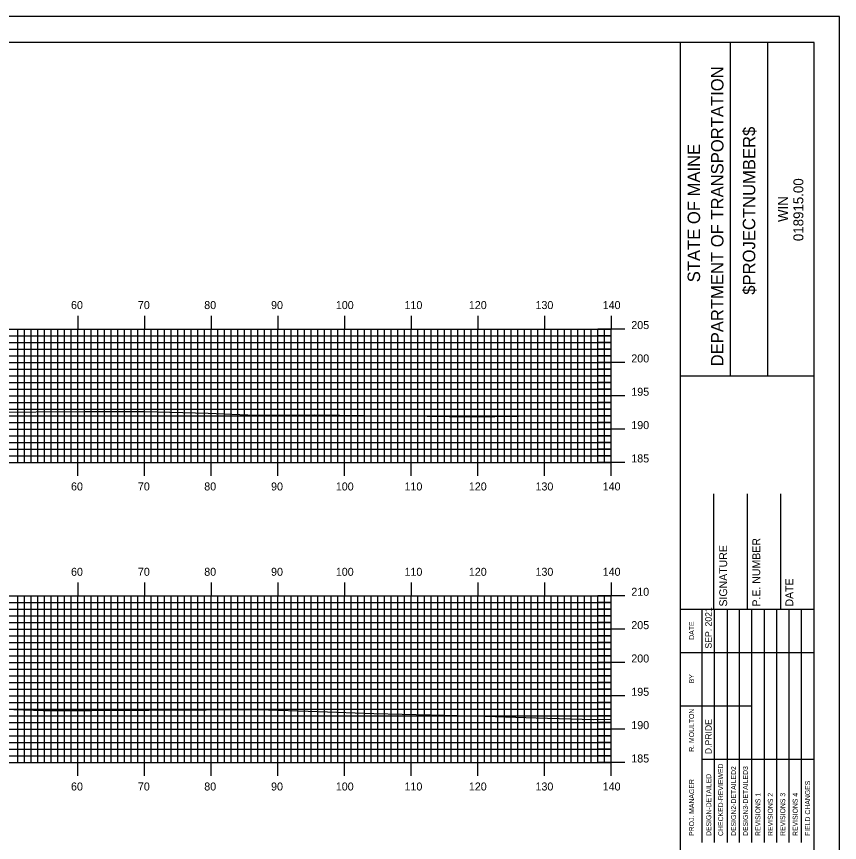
# Model space of a CAD drawing. Extents: x 1814128 to 1814471, y 442591 to 442811.
# Drawn here: x 1814344.8 to 1814468.2, y 442686.7 to 442810.5 of the extents above; entities that cross this region are included whole.
import ezdxf

# ---------------------------------------------------------------- set-up
doc = ezdxf.new("R2010")
doc.units = 0
for name, color, linetype in [('BORDER', 7, 'Continuous'), ('H_V ANNOTATION', 7, 'Continuous'), ('MAJOR', 7, 'Continuous'), ('MINOR', 7, 'Continuous'), ('PLOT BOUNDARY', 7, 'Continuous'), ('S_Roadway_Centerline', 7, 'Continuous')]:
    doc.layers.add(name, color=color, linetype=linetype)

msp = doc.modelspace()

# ---------------------------------------------------------------- linework, layer by layer
at = {"layer": 'BORDER'}
for p, q in [((1814444.39, 442596.67), (1814444.39, 442806.67)), ((1814451.85, 442756.66), (1814451.85, 442806.66)), ((1814457.44, 442756.66), (1814457.44, 442806.66)), ((1814444.4, 442756.65), (1814464.39, 442756.65)), ((1814449.39, 442721.67), (1814449.39, 442738.97)), ((1814454.39, 442721.67), (1814454.39, 442738.97)), ((1814459.39, 442721.67), (1814459.39, 442738.97)), ((1814444.39, 442721.67), (1814464.39, 442721.67))]:
    msp.add_line(p, q, dxfattribs=at)
msp.add_lwpolyline([(1814144.39, 442596.67), (1814464.39, 442596.67), (1814464.39, 442806.67), (1814144.39, 442806.67)], close=True, dxfattribs=at)
for points in [[(1814447.62, 442715.17), (1814447.62, 442721.67)], [(1814449.49, 442686.68), (1814449.49, 442721.67)], [(1814451.35, 442721.67), (1814451.35, 442686.68)], [(1814453.22, 442686.68), (1814453.22, 442721.67)], [(1814455.08, 442686.68), (1814455.08, 442721.67)], [(1814456.94, 442686.68), (1814456.94, 442721.67)], [(1814458.81, 442686.68), (1814458.81, 442721.67)], [(1814460.67, 442686.68), (1814460.67, 442721.67)], [(1814462.53, 442686.68), (1814462.53, 442721.67)], [(1814447.63, 442686.68), (1814447.63, 442720.26)], [(1814444.39, 442715.17), (1814464.39, 442715.17)], [(1814444.39, 442707.17), (1814447.63, 442707.17)], [(1814447.62, 442707.17), (1814455.08, 442707.17)], [(1814447.62, 442699.17), (1814464.39, 442699.17)]]:
    msp.add_lwpolyline(points, dxfattribs=at)
at = {"layer": 'MAJOR'}
for p, q in [((1814353.99, 442765.67), (1814353.99, 442763.67)), ((1814363.99, 442765.67), (1814363.99, 442763.67)), ((1814373.99, 442765.67), (1814373.99, 442763.67)), ((1814383.99, 442765.67), (1814383.99, 442763.67)), ((1814393.99, 442765.67), (1814393.99, 442763.67)), ((1814403.99, 442765.67), (1814403.99, 442763.67)), ((1814413.99, 442765.67), (1814413.99, 442763.67)), ((1814423.99, 442765.67), (1814423.99, 442763.67)), ((1814433.99, 442765.67), (1814433.99, 442763.67)), ((1814153.99, 442763.67), (1814433.99, 442763.67)), ((1814153.99, 442763.67), (1814433.99, 442763.67)), ((1814353.99, 442743.67), (1814353.99, 442763.67)), ((1814363.99, 442743.67), (1814363.99, 442763.67)), ((1814373.99, 442743.67), (1814373.99, 442763.67)), ((1814383.99, 442743.67), (1814383.99, 442763.67)), ((1814393.99, 442743.67), (1814393.99, 442763.67)), ((1814403.99, 442743.67), (1814403.99, 442763.67)), ((1814413.99, 442743.67), (1814413.99, 442763.67)), ((1814423.99, 442743.67), (1814423.99, 442763.67)), ((1814436, 442763.67), (1814431.99, 442763.67)), ((1814433.99, 442743.67), (1814433.99, 442763.67)), ((1814433.99, 442743.67), (1814433.99, 442763.67)), ((1814153.99, 442758.67), (1814433.99, 442758.67)), ((1814436, 442758.67), (1814431.99, 442758.67)), ((1814153.99, 442753.67), (1814433.99, 442753.67)), ((1814436, 442753.67), (1814431.99, 442753.67)), ((1814153.99, 442748.67), (1814433.99, 442748.67)), ((1814436, 442748.67), (1814431.99, 442748.67)), ((1814153.99, 442743.67), (1814433.99, 442743.67)), ((1814153.99, 442743.67), (1814433.99, 442743.67)), ((1814353.99, 442741.66), (1814353.99, 442743.67)), ((1814363.99, 442741.66), (1814363.99, 442743.67)), ((1814373.99, 442741.66), (1814373.99, 442743.67)), ((1814383.99, 442741.66), (1814383.99, 442743.67)), ((1814393.99, 442741.66), (1814393.99, 442743.67)), ((1814403.99, 442741.66), (1814403.99, 442743.67)), ((1814413.99, 442741.66), (1814413.99, 442743.67)), ((1814423.99, 442741.66), (1814423.99, 442743.67)), ((1814436, 442743.67), (1814431.99, 442743.67)), ((1814433.99, 442741.66), (1814433.99, 442743.67)), ((1814353.99, 442725.67), (1814353.99, 442723.67)), ((1814363.99, 442725.67), (1814363.99, 442723.67)), ((1814373.99, 442725.67), (1814373.99, 442723.67)), ((1814383.99, 442725.67), (1814383.99, 442723.67)), ((1814393.99, 442725.67), (1814393.99, 442723.67)), ((1814403.99, 442725.67), (1814403.99, 442723.67)), ((1814413.99, 442725.67), (1814413.99, 442723.67)), ((1814423.99, 442725.67), (1814423.99, 442723.67)), ((1814433.99, 442725.67), (1814433.99, 442723.67)), ((1814153.99, 442723.67), (1814433.99, 442723.67)), ((1814153.99, 442723.67), (1814433.99, 442723.67)), ((1814353.99, 442698.67), (1814353.99, 442723.67)), ((1814363.99, 442698.67), (1814363.99, 442723.67)), ((1814373.99, 442698.67), (1814373.99, 442723.67)), ((1814383.99, 442698.67), (1814383.99, 442723.67)), ((1814393.99, 442698.67), (1814393.99, 442723.67)), ((1814403.99, 442698.67), (1814403.99, 442723.67)), ((1814413.99, 442698.67), (1814413.99, 442723.67)), ((1814423.99, 442698.67), (1814423.99, 442723.67)), ((1814436, 442723.67), (1814431.99, 442723.67)), ((1814433.99, 442698.67), (1814433.99, 442723.67)), ((1814433.99, 442698.67), (1814433.99, 442723.67)), ((1814153.99, 442718.67), (1814433.99, 442718.67)), ((1814436, 442718.67), (1814431.99, 442718.67)), ((1814153.99, 442713.67), (1814433.99, 442713.67)), ((1814436, 442713.67), (1814431.99, 442713.67)), ((1814153.99, 442708.67), (1814433.99, 442708.67)), ((1814436, 442708.67), (1814431.99, 442708.67)), ((1814153.99, 442703.67), (1814433.99, 442703.67)), ((1814436, 442703.67), (1814431.99, 442703.67)), ((1814153.99, 442698.67), (1814433.99, 442698.67)), ((1814153.99, 442698.67), (1814433.99, 442698.67)), ((1814353.99, 442696.66), (1814353.99, 442698.67)), ((1814363.99, 442696.66), (1814363.99, 442698.67)), ((1814373.99, 442696.66), (1814373.99, 442698.67)), ((1814383.99, 442696.66), (1814383.99, 442698.67)), ((1814393.99, 442696.66), (1814393.99, 442698.67)), ((1814403.99, 442696.66), (1814403.99, 442698.67)), ((1814413.99, 442696.66), (1814413.99, 442698.67)), ((1814423.99, 442696.66), (1814423.99, 442698.67)), ((1814436, 442698.67), (1814431.99, 442698.67)), ((1814433.99, 442696.66), (1814433.99, 442698.67))]:
    msp.add_line(p, q, dxfattribs=at)
at = {"layer": 'MINOR'}
for p, q in [((1814344.99, 442743.67), (1814344.99, 442763.67)), ((1814345.99, 442743.67), (1814345.99, 442763.67)), ((1814346.99, 442743.67), (1814346.99, 442763.67)), ((1814347.99, 442743.67), (1814347.99, 442763.67)), ((1814348.99, 442743.67), (1814348.99, 442763.67)), ((1814349.99, 442743.67), (1814349.99, 442763.67)), ((1814350.99, 442743.67), (1814350.99, 442763.67)), ((1814351.99, 442743.67), (1814351.99, 442763.67)), ((1814352.99, 442743.67), (1814352.99, 442763.67)), ((1814354.99, 442743.67), (1814354.99, 442763.67)), ((1814355.99, 442743.67), (1814355.99, 442763.67)), ((1814356.99, 442743.67), (1814356.99, 442763.67)), ((1814357.99, 442743.67), (1814357.99, 442763.67)), ((1814358.99, 442743.67), (1814358.99, 442763.67)), ((1814359.99, 442743.67), (1814359.99, 442763.67)), ((1814360.99, 442743.67), (1814360.99, 442763.67)), ((1814361.99, 442743.67), (1814361.99, 442763.67)), ((1814362.99, 442743.67), (1814362.99, 442763.67)), ((1814364.99, 442743.67), (1814364.99, 442763.67)), ((1814365.99, 442743.67), (1814365.99, 442763.67)), ((1814366.99, 442743.67), (1814366.99, 442763.67)), ((1814367.99, 442743.67), (1814367.99, 442763.67)), ((1814368.99, 442743.67), (1814368.99, 442763.67)), ((1814369.99, 442743.67), (1814369.99, 442763.67)), ((1814370.99, 442743.67), (1814370.99, 442763.67)), ((1814371.99, 442743.67), (1814371.99, 442763.67)), ((1814372.99, 442743.67), (1814372.99, 442763.67)), ((1814374.99, 442743.67), (1814374.99, 442763.67)), ((1814375.99, 442743.67), (1814375.99, 442763.67)), ((1814376.99, 442743.67), (1814376.99, 442763.67)), ((1814377.99, 442743.67), (1814377.99, 442763.67)), ((1814378.99, 442743.67), (1814378.99, 442763.67)), ((1814379.99, 442743.67), (1814379.99, 442763.67)), ((1814380.99, 442743.67), (1814380.99, 442763.67)), ((1814381.99, 442743.67), (1814381.99, 442763.67)), ((1814382.99, 442743.67), (1814382.99, 442763.67)), ((1814384.99, 442743.67), (1814384.99, 442763.67)), ((1814385.99, 442743.67), (1814385.99, 442763.67)), ((1814386.99, 442743.67), (1814386.99, 442763.67)), ((1814387.99, 442743.67), (1814387.99, 442763.67)), ((1814388.99, 442743.67), (1814388.99, 442763.67)), ((1814389.99, 442743.67), (1814389.99, 442763.67)), ((1814390.99, 442743.67), (1814390.99, 442763.67)), ((1814391.99, 442743.67), (1814391.99, 442763.67)), ((1814392.99, 442743.67), (1814392.99, 442763.67)), ((1814394.99, 442743.67), (1814394.99, 442763.67)), ((1814395.99, 442743.67), (1814395.99, 442763.67)), ((1814396.99, 442743.67), (1814396.99, 442763.67)), ((1814397.99, 442743.67), (1814397.99, 442763.67)), ((1814398.99, 442743.67), (1814398.99, 442763.67)), ((1814399.99, 442743.67), (1814399.99, 442763.67)), ((1814400.99, 442743.67), (1814400.99, 442763.67)), ((1814401.99, 442743.67), (1814401.99, 442763.67)), ((1814402.99, 442743.67), (1814402.99, 442763.67)), ((1814404.99, 442743.67), (1814404.99, 442763.67)), ((1814405.99, 442743.67), (1814405.99, 442763.67)), ((1814406.99, 442743.67), (1814406.99, 442763.67)), ((1814407.99, 442743.67), (1814407.99, 442763.67)), ((1814408.99, 442743.67), (1814408.99, 442763.67)), ((1814409.99, 442743.67), (1814409.99, 442763.67)), ((1814410.99, 442743.67), (1814410.99, 442763.67)), ((1814411.99, 442743.67), (1814411.99, 442763.67)), ((1814412.99, 442743.67), (1814412.99, 442763.67)), ((1814414.99, 442743.67), (1814414.99, 442763.67)), ((1814415.99, 442743.67), (1814415.99, 442763.67)), ((1814416.99, 442743.67), (1814416.99, 442763.67)), ((1814417.99, 442743.67), (1814417.99, 442763.67)), ((1814418.99, 442743.67), (1814418.99, 442763.67)), ((1814419.99, 442743.67), (1814419.99, 442763.67)), ((1814420.99, 442743.67), (1814420.99, 442763.67)), ((1814421.99, 442743.67), (1814421.99, 442763.67)), ((1814422.99, 442743.67), (1814422.99, 442763.67)), ((1814424.99, 442743.67), (1814424.99, 442763.67)), ((1814425.99, 442743.67), (1814425.99, 442763.67)), ((1814426.99, 442743.67), (1814426.99, 442763.67)), ((1814427.99, 442743.67), (1814427.99, 442763.67)), ((1814428.99, 442743.67), (1814428.99, 442763.67)), ((1814429.99, 442743.67), (1814429.99, 442763.67)), ((1814430.99, 442743.67), (1814430.99, 442763.67)), ((1814431.99, 442743.67), (1814431.99, 442763.67)), ((1814432.99, 442743.67), (1814432.99, 442763.67)), ((1814153.99, 442762.67), (1814433.99, 442762.67)), ((1814433.99, 442762.67), (1814431.99, 442762.67)), ((1814153.99, 442761.67), (1814433.99, 442761.67)), ((1814433.99, 442761.67), (1814431.99, 442761.67)), ((1814153.99, 442760.67), (1814433.99, 442760.67)), ((1814433.99, 442760.67), (1814431.99, 442760.67)), ((1814153.99, 442759.67), (1814433.99, 442759.67)), ((1814433.99, 442759.67), (1814431.99, 442759.67)), ((1814153.99, 442757.67), (1814433.99, 442757.67)), ((1814433.99, 442757.67), (1814431.99, 442757.67)), ((1814153.99, 442756.67), (1814433.99, 442756.67)), ((1814433.99, 442756.67), (1814431.99, 442756.67)), ((1814153.99, 442755.67), (1814433.99, 442755.67)), ((1814433.99, 442755.67), (1814431.99, 442755.67)), ((1814153.99, 442754.67), (1814433.99, 442754.67)), ((1814433.99, 442754.67), (1814431.99, 442754.67)), ((1814153.99, 442752.67), (1814433.99, 442752.67)), ((1814433.99, 442752.67), (1814431.99, 442752.67)), ((1814153.99, 442751.67), (1814433.99, 442751.67)), ((1814433.99, 442751.67), (1814431.99, 442751.67)), ((1814153.99, 442750.67), (1814433.99, 442750.67)), ((1814433.99, 442750.67), (1814431.99, 442750.67)), ((1814153.99, 442749.67), (1814433.99, 442749.67)), ((1814433.99, 442749.67), (1814431.99, 442749.67)), ((1814153.99, 442747.67), (1814433.99, 442747.67)), ((1814433.99, 442747.67), (1814431.99, 442747.67)), ((1814153.99, 442746.67), (1814433.99, 442746.67)), ((1814433.99, 442746.67), (1814431.99, 442746.67)), ((1814153.99, 442745.67), (1814433.99, 442745.67)), ((1814433.99, 442745.67), (1814431.99, 442745.67)), ((1814153.99, 442744.67), (1814433.99, 442744.67)), ((1814433.99, 442744.67), (1814431.99, 442744.67)), ((1814344.99, 442698.67), (1814344.99, 442723.67)), ((1814345.99, 442698.67), (1814345.99, 442723.67)), ((1814346.99, 442698.67), (1814346.99, 442723.67)), ((1814347.99, 442698.67), (1814347.99, 442723.67)), ((1814348.99, 442698.67), (1814348.99, 442723.67)), ((1814349.99, 442698.67), (1814349.99, 442723.67)), ((1814350.99, 442698.67), (1814350.99, 442723.67)), ((1814351.99, 442698.67), (1814351.99, 442723.67)), ((1814352.99, 442698.67), (1814352.99, 442723.67)), ((1814354.99, 442698.67), (1814354.99, 442723.67)), ((1814355.99, 442698.67), (1814355.99, 442723.67)), ((1814356.99, 442698.67), (1814356.99, 442723.67)), ((1814357.99, 442698.67), (1814357.99, 442723.67)), ((1814358.99, 442698.67), (1814358.99, 442723.67)), ((1814359.99, 442698.67), (1814359.99, 442723.67)), ((1814360.99, 442698.67), (1814360.99, 442723.67)), ((1814361.99, 442698.67), (1814361.99, 442723.67)), ((1814362.99, 442698.67), (1814362.99, 442723.67)), ((1814364.99, 442698.67), (1814364.99, 442723.67)), ((1814365.99, 442698.67), (1814365.99, 442723.67)), ((1814366.99, 442698.67), (1814366.99, 442723.67)), ((1814367.99, 442698.67), (1814367.99, 442723.67)), ((1814368.99, 442698.67), (1814368.99, 442723.67)), ((1814369.99, 442698.67), (1814369.99, 442723.67)), ((1814370.99, 442698.67), (1814370.99, 442723.67)), ((1814371.99, 442698.67), (1814371.99, 442723.67)), ((1814372.99, 442698.67), (1814372.99, 442723.67)), ((1814374.99, 442698.67), (1814374.99, 442723.67)), ((1814375.99, 442698.67), (1814375.99, 442723.67)), ((1814376.99, 442698.67), (1814376.99, 442723.67)), ((1814377.99, 442698.67), (1814377.99, 442723.67)), ((1814378.99, 442698.67), (1814378.99, 442723.67)), ((1814379.99, 442698.67), (1814379.99, 442723.67)), ((1814380.99, 442698.67), (1814380.99, 442723.67)), ((1814381.99, 442698.67), (1814381.99, 442723.67)), ((1814382.99, 442698.67), (1814382.99, 442723.67)), ((1814384.99, 442698.67), (1814384.99, 442723.67)), ((1814385.99, 442698.67), (1814385.99, 442723.67)), ((1814386.99, 442698.67), (1814386.99, 442723.67)), ((1814387.99, 442698.67), (1814387.99, 442723.67)), ((1814388.99, 442698.67), (1814388.99, 442723.67)), ((1814389.99, 442698.67), (1814389.99, 442723.67)), ((1814390.99, 442698.67), (1814390.99, 442723.67)), ((1814391.99, 442698.67), (1814391.99, 442723.67)), ((1814392.99, 442698.67), (1814392.99, 442723.67)), ((1814394.99, 442698.67), (1814394.99, 442723.67)), ((1814395.99, 442698.67), (1814395.99, 442723.67)), ((1814396.99, 442698.67), (1814396.99, 442723.67)), ((1814397.99, 442698.67), (1814397.99, 442723.67)), ((1814398.99, 442698.67), (1814398.99, 442723.67)), ((1814399.99, 442698.67), (1814399.99, 442723.67)), ((1814400.99, 442698.67), (1814400.99, 442723.67)), ((1814401.99, 442698.67), (1814401.99, 442723.67)), ((1814402.99, 442698.67), (1814402.99, 442723.67)), ((1814404.99, 442698.67), (1814404.99, 442723.67)), ((1814405.99, 442698.67), (1814405.99, 442723.67)), ((1814406.99, 442698.67), (1814406.99, 442723.67)), ((1814407.99, 442698.67), (1814407.99, 442723.67)), ((1814408.99, 442698.67), (1814408.99, 442723.67)), ((1814409.99, 442698.67), (1814409.99, 442723.67)), ((1814410.99, 442698.67), (1814410.99, 442723.67)), ((1814411.99, 442698.67), (1814411.99, 442723.67)), ((1814412.99, 442698.67), (1814412.99, 442723.67)), ((1814414.99, 442698.67), (1814414.99, 442723.67)), ((1814415.99, 442698.67), (1814415.99, 442723.67)), ((1814416.99, 442698.67), (1814416.99, 442723.67)), ((1814417.99, 442698.67), (1814417.99, 442723.67)), ((1814418.99, 442698.67), (1814418.99, 442723.67)), ((1814419.99, 442698.67), (1814419.99, 442723.67)), ((1814420.99, 442698.67), (1814420.99, 442723.67)), ((1814421.99, 442698.67), (1814421.99, 442723.67)), ((1814422.99, 442698.67), (1814422.99, 442723.67)), ((1814424.99, 442698.67), (1814424.99, 442723.67)), ((1814425.99, 442698.67), (1814425.99, 442723.67)), ((1814426.99, 442698.67), (1814426.99, 442723.67)), ((1814427.99, 442698.67), (1814427.99, 442723.67)), ((1814428.99, 442698.67), (1814428.99, 442723.67)), ((1814429.99, 442698.67), (1814429.99, 442723.67)), ((1814430.99, 442698.67), (1814430.99, 442723.67)), ((1814431.99, 442698.67), (1814431.99, 442723.67)), ((1814432.99, 442698.67), (1814432.99, 442723.67)), ((1814153.99, 442722.67), (1814433.99, 442722.67)), ((1814153.99, 442721.67), (1814433.99, 442721.67)), ((1814433.99, 442722.67), (1814431.99, 442722.67)), ((1814433.99, 442721.67), (1814431.99, 442721.67)), ((1814153.99, 442720.67), (1814433.99, 442720.67)), ((1814433.99, 442720.67), (1814431.99, 442720.67)), ((1814153.99, 442719.67), (1814433.99, 442719.67)), ((1814433.99, 442719.67), (1814431.99, 442719.67)), ((1814153.99, 442717.67), (1814433.99, 442717.67)), ((1814153.99, 442716.67), (1814433.99, 442716.67)), ((1814433.99, 442717.67), (1814431.99, 442717.67)), ((1814433.99, 442716.67), (1814431.99, 442716.67)), ((1814153.99, 442715.67), (1814433.99, 442715.67)), ((1814433.99, 442715.67), (1814431.99, 442715.67)), ((1814153.99, 442714.67), (1814433.99, 442714.67)), ((1814433.99, 442714.67), (1814431.99, 442714.67)), ((1814153.99, 442712.67), (1814433.99, 442712.67)), ((1814153.99, 442711.67), (1814433.99, 442711.67)), ((1814433.99, 442712.67), (1814431.99, 442712.67)), ((1814433.99, 442711.67), (1814431.99, 442711.67)), ((1814153.99, 442710.67), (1814433.99, 442710.67)), ((1814433.99, 442710.67), (1814431.99, 442710.67)), ((1814153.99, 442709.67), (1814433.99, 442709.67)), ((1814433.99, 442709.67), (1814431.99, 442709.67)), ((1814153.99, 442707.67), (1814433.99, 442707.67)), ((1814153.99, 442706.67), (1814433.99, 442706.67)), ((1814433.99, 442707.67), (1814431.99, 442707.67)), ((1814433.99, 442706.67), (1814431.99, 442706.67)), ((1814153.99, 442705.67), (1814433.99, 442705.67)), ((1814433.99, 442705.67), (1814431.99, 442705.67)), ((1814153.99, 442704.67), (1814433.99, 442704.67)), ((1814433.99, 442704.67), (1814431.99, 442704.67)), ((1814153.99, 442702.67), (1814433.99, 442702.67)), ((1814153.99, 442701.67), (1814433.99, 442701.67)), ((1814433.99, 442702.67), (1814431.99, 442702.67)), ((1814433.99, 442701.67), (1814431.99, 442701.67)), ((1814153.99, 442700.67), (1814433.99, 442700.67)), ((1814433.99, 442700.67), (1814431.99, 442700.67)), ((1814153.99, 442699.67), (1814433.99, 442699.67)), ((1814433.99, 442699.67), (1814431.99, 442699.67))]:
    msp.add_line(p, q, dxfattribs=at)
at = {"layer": 'PLOT BOUNDARY'}
msp.add_lwpolyline([(1814128.21, 442590.55), (1814468.21, 442590.55), (1814468.21, 442810.55), (1814128.21, 442810.55)], close=True, dxfattribs=at)
at = {"layer": 'S_Roadway_Centerline'}
for points in [[(1814340.44, 442751.22), (1814354.92, 442751.33), (1814364, 442751.32), (1814373.52, 442751.07), (1814380.7, 442750.78), (1814389.52, 442750.79), (1814396.94, 442750.73), (1814403.1, 442750.68), (1814413.04, 442750.53), (1814420.07, 442750.62), (1814430.03, 442750.71), (1814433.99, 442750.67)], [(1814341.4, 442706.74), (1814348.79, 442706.48), (1814356.11, 442706.45), (1814373.25, 442706.57), (1814381.06, 442706.62), (1814390.02, 442706.34), (1814398.38, 442706.03), (1814406.87, 442705.82), (1814415.07, 442705.63), (1814422.72, 442705.35), (1814431.34, 442705.13), (1814433.99, 442705.19)]]:
    msp.add_lwpolyline(points, dxfattribs=at)

# ---------------------------------------------------------------- texts
at = {"layer": 'BORDER'}
for s, height, p in [('DEPARTMENT OF TRANSPORTATION', 1.8635, (1814450.81, 442758.08)), ('$PROJECTNUMBER$', 1.8635, (1814455.58, 442768.82)), ('STATE OF MAINE', 1.8635, (1814447.3, 442770.69)), ('018915.00', 1.491, (1814462.79, 442776.86)), ('WIN', 1.491, (1814460.47, 442779.73)), ('P.E. NUMBER', 1.1811, (1814456.32, 442722.06)), ('SIGNATURE', 1.181, (1814451.36, 442722.06)), ('DATE', 1.181, (1814461.28, 442722.06)), ('SEP. 2021', 0.969, (1814449.04, 442715.76)), ('DATE', 0.743, (1814446.4, 442717.08)), ('BY', 0.743, (1814446.4, 442710.54)), ('R. MOULTON', 0.745, (1814446.4, 442700.28)), ('D.PRIDE', 0.969, (1814449.04, 442699.92)), ('CHECKED-REVIEWED', 0.7455, (1814450.76, 442687.65)), ('DESIGN2-DETAILED2', 0.7455, (1814452.69, 442687.65)), ('DESIGN3-DETAILED3', 0.7455, (1814454.48, 442687.65)), ('PROJ. MANAGER', 0.7455, (1814446.4, 442687.65)), ('DESIGN-DETAILED', 0.7455, (1814448.97, 442687.65)), ('FIELD CHANGES', 0.7455, (1814463.8, 442687.65)), ('REVISIONS 1', 0.7455, (1814456.35, 442687.65)), ('REVISIONS 2', 0.7455, (1814458.21, 442687.65)), ('REVISIONS 3', 0.7455, (1814460.07, 442687.65)), ('REVISIONS 4', 0.7455, (1814461.94, 442687.65))]:
    msp.add_text(s, height=height, rotation=90, dxfattribs=at).set_placement(p)
at = {"layer": 'H_V ANNOTATION'}
for s, p in [('60', (1814352.97, 442766.67)), ('70', (1814363, 442766.67)), ('80', (1814372.95, 442766.67)), ('90', (1814382.97, 442766.67)), ('100', (1814392.68, 442766.67)), ('110', (1814402.98, 442766.67)), ('120', (1814412.63, 442766.67)), ('130', (1814422.62, 442766.67)), ('140', (1814432.7, 442766.67)), ('205', (1814436.99, 442763.67)), ('200', (1814436.99, 442758.67)), ('195', (1814436.99, 442753.67)), ('190', (1814436.99, 442748.67)), ('185', (1814436.99, 442743.67)), ('60', (1814352.97, 442739.47)), ('70', (1814363, 442739.47)), ('80', (1814372.95, 442739.47)), ('90', (1814382.97, 442739.47)), ('100', (1814392.68, 442739.47)), ('110', (1814402.98, 442739.47)), ('120', (1814412.63, 442739.47)), ('130', (1814422.62, 442739.47)), ('140', (1814432.7, 442739.47)), ('60', (1814352.97, 442726.67)), ('70', (1814363, 442726.67)), ('80', (1814372.95, 442726.67)), ('90', (1814382.97, 442726.67)), ('100', (1814392.68, 442726.67)), ('110', (1814402.98, 442726.67)), ('120', (1814412.63, 442726.67)), ('130', (1814422.62, 442726.67)), ('140', (1814432.7, 442726.67)), ('210', (1814436.99, 442723.67)), ('205', (1814436.99, 442718.67)), ('200', (1814436.99, 442713.67)), ('195', (1814436.99, 442708.67)), ('190', (1814436.99, 442703.67)), ('185', (1814436.99, 442698.67)), ('60', (1814352.97, 442694.47)), ('70', (1814363, 442694.47)), ('80', (1814372.95, 442694.47)), ('90', (1814382.97, 442694.47)), ('100', (1814392.68, 442694.47)), ('110', (1814402.98, 442694.47)), ('120', (1814412.63, 442694.47)), ('130', (1814422.62, 442694.47)), ('140', (1814432.7, 442694.47))]:
    msp.add_text(s, height=1.2, dxfattribs=at).set_placement(p)

doc.saveas('drawing.dxf')
